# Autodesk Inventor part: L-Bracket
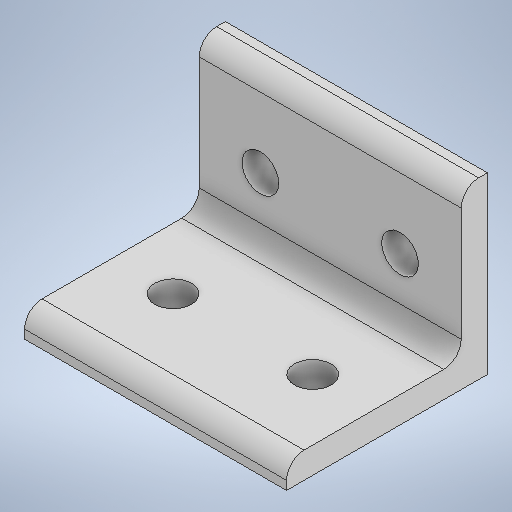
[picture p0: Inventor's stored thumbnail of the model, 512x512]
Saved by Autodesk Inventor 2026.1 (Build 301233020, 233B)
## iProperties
Created: 2026-11
Part Number: L-Bracket
Material: Generic
Document SubType Name: Modeling
Designer: hp
Density: 1 g/cm^3
Appearance: Default
Author: hp
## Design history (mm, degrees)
sketch "Sketch1"
  geometry: L1 (0, 0)-(30, 0); L2 (30, 0)-(30, 20); L3 (30, 20)-(0, 20); L4 (0, 20)-(0, 0); L5 (0, 3)-(30, 3); L6 (15, 20)-(15, 0); C1 r 2.1 at (7, 10); C2 r 2.1 at (23, 10); 1 further point
  constraints: 12 end point, 3 midpoint, 2 centre point, 2 parallel, 2 perpendicular, 2 point on line, 1 horizontal, 1 horizontal alignment, 1 symmetric about line, 1 other
  dimensions: "d0" = 30 distance of L3.end L2.end; "d1" = 20 distance of L1.end L2.end; "d2" = 3 distance between parallel lines of L1 L5; "d3" = 4.2 diameter of C1; "d4" = 7 distance from line of L4 C1.centre
extrude "Extrusion1" new body sketch "Sketch1" distance "d5" = 3 (= d2); taper "d6" = 0 deg
extrude "Extrusion2" join sketch "Sketch1" distance "d7" = 20 (= d1); taper "d8" = 0 deg
sketch "Sketch3"
  geometry: L1 (0, -20)-(30, -20); L2 (30, -20)-(30, 0); L3 (30, 0)-(0, 0); L4 (0, 0)-(0, -20); L5 (0, -17)-(30, -17); L6 (15, 0)-(15, -20); C1 r 2.1 at (7, -10); C2 r 2.1 at (23, -10); 3 further points
  constraints: 12 end point, 3 midpoint, 2 centre point, 2 parallel, 2 perpendicular, 2 point on line, 1 coincident, 1 horizontal, 1 horizontal alignment, 1 symmetric about line, 1 other
  dimensions: "d16" = 30 distance of L3.end L2.end; "d17" = 20 distance of L1.end L2.end; "d18" = 3 distance between parallel lines of L1 L5; "d19" = 4.2 diameter of C1; "d20" = 7 distance from line of L4 C1.centre
extrude "Extrusion4" cut sketch "Sketch3" stored distance "d21" = 10; taper "d22" = 0 deg
fillet "Fillet1" dims "d23" = 2
body "Solid1"
